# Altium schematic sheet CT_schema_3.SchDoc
size 283 x 147 mm
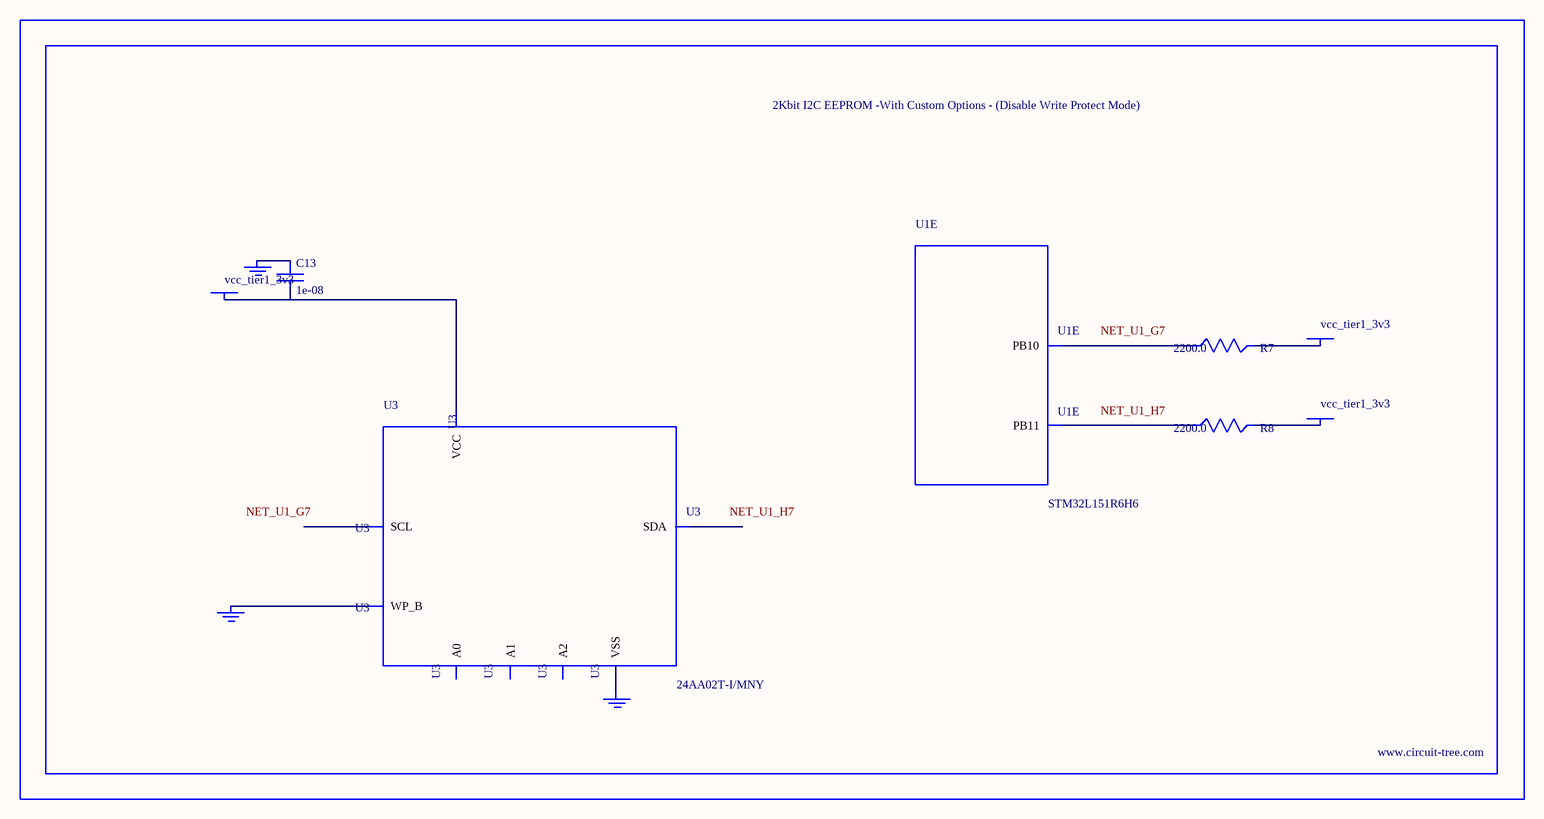
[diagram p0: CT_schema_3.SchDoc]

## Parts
BORDER2  (no value)
C13  1e-08  [C0402]
GND_INSTANCE_2_0  (no value)
GND_INSTANCE_2_1  (no value)
GND_INSTANCE_2_2  (no value)
POWER_INSTANCE_2_0  vcc_tier1_3v3
POWER_INSTANCE_2_1  vcc_tier1_3v3
POWER_INSTANCE_2_2  vcc_tier1_3v3
R7  2200.0  [R0603]
R8  2200.0  [R0603]
U1  STM32L151R6H6  [TFBGA64]  (part E of 6)
U3  24AA02T-I/MNY  [TDFN-8/6MM]

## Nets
NetC13_1: C13.1 GND_INSTANCE_2_1.0(GND)
NetC13_2: C13.2 POWER_INSTANCE_2_0.0(PWR) U3.8(VCC)
NetGND_INSTANCE_2_0_0: GND_INSTANCE_2_0.0(GND) U3.7(WP_B)
NetGND_INSTANCE_2_2_0: GND_INSTANCE_2_2.0(GND) U3.4(VSS)
NetPOWER_INSTANCE_2_1_0: POWER_INSTANCE_2_1.0(PWR) R7.2
NetPOWER_INSTANCE_2_2_0: POWER_INSTANCE_2_2.0(PWR) R8.2
NetR7_1: R7.1 U1.G7(PB10)
NetR8_1: R8.1 U1.H7(PB11)

Not connected (* = marked no-connect by the designer): U3 1(A0) 2(A1) 3(A2) 5(SDA) 6(SCL)

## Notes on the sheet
- Labels drawn without touching a wire or pin: NET_U1_G7, NET_U1_H7

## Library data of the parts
BORDER2 = BORDER_PAGE2
C13 = C0402C103K3RAC
GND_INSTANCE_2_0-GND_INSTANCE_2_2 = GND
POWER_INSTANCE_2_0-POWER_INSTANCE_2_2 = PWR
R7 R8 = RC0603JR-072K2L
